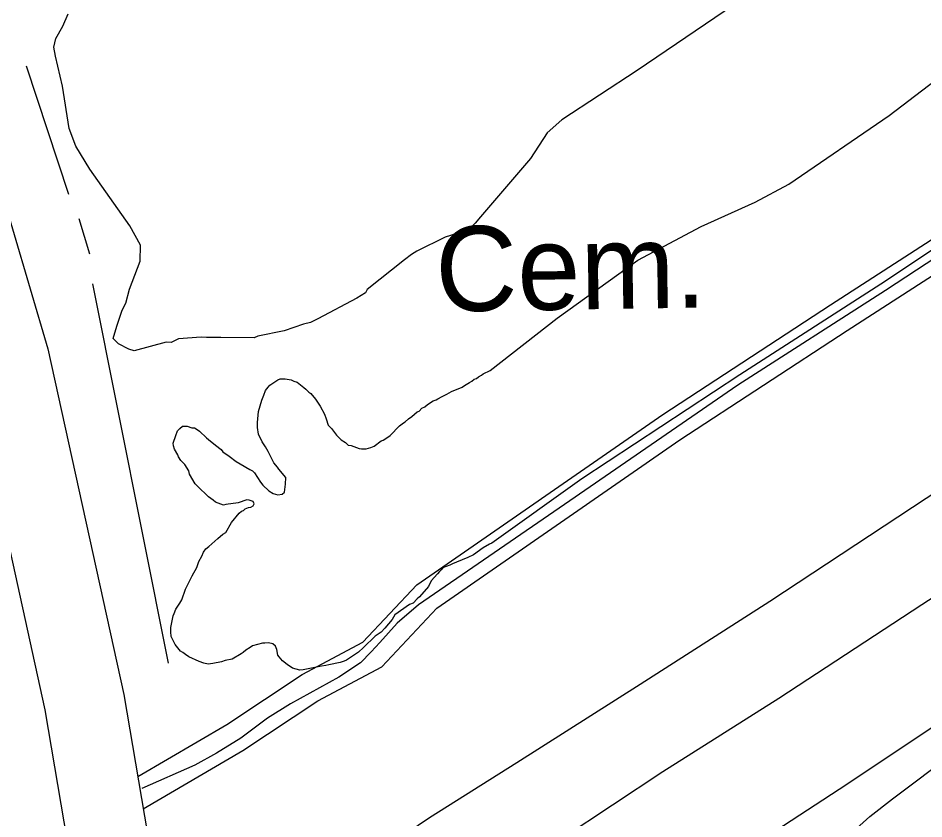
# Model space of a CAD drawing. Extents: x 3812694 to 3850888, y 319753 to 345638.
# Drawn here: x 3827334 to 3828221, y 341766 to 342550 of the extents above; entities that cross this region are included whole.
import ezdxf

# ---------------------------------------------------------------- set-up
doc = ezdxf.new("R2010")
doc.units = 0
for name, color, linetype in [('V-DTCH-CNTR', 7, 'Continuous'), ('V-GRID-MAJR', 7, 'Continuous'), ('V-ROAD-CNTR', 7, 'Continuous'), ('V-SITE-OTLN-IDEN', 7, 'Continuous'), ('V-SITE-VEGE', 7, 'Continuous'), ('V-TOPO-SHOR', 7, 'Continuous')]:
    doc.layers.add(name, color=color, linetype=linetype)

msp = doc.modelspace()

# ---------------------------------------------------------------- linework, layer by layer
at = {"layer": 'V-DTCH-CNTR'}
for points in [[(3828407.32, 342440.64), (3828293.22, 342355.47), (3828183.34, 342283.15), (3828038.76, 342190.5), (3827869.24, 342073.82), (3827726.16, 341975.48), (3827705.4, 341957.61), (3827688.23, 341938.67), (3827679.91, 341929.46), (3827669.51, 341918.72), (3827648.26, 341904.45)], [(3827648.26, 341904.45), (3827601.05, 341878.45), (3827578.41, 341864.28), (3827552.23, 341844.69), (3827528.42, 341830.14), (3827507.35, 341818.28), (3827455.46, 341795.38)]]:
    msp.add_lwpolyline(points, dxfattribs=at)
at = {"layer": 'V-GRID-MAJR'}
msp.add_spline([(3827552.14, 325339.08), (3827461.39, 331396.12), (3827370.6, 337456.24), (3827279.8, 343516.36), (3827279.75, 343519.45)], degree=3, dxfattribs=at)
at = {"layer": 'V-ROAD-CNTR'}
for points in [[(3826888.69, 343517.19), (3827149.47, 342673.63), (3827287.1, 342206.56), (3827360.53, 341872.65), (3827388.64, 341707), (3827434.74, 341341.67), (3827456.33, 341039.03), (3827475.62, 340587.6), (3827499.99, 340026.68), (3827519.29, 339556.06), (3827541.5, 339155.86), (3827581.61, 338852.35), (3827660.21, 338530.82), (3827812.32, 338143.51), (3827979.35, 337772.54), (3828135.82, 337439.21), (3828238.83, 337215.31)], [(3826963.8, 343518.33), (3827224.65, 342696.63), (3827363.29, 342226.13), (3827437.73, 341887.68), (3827466.42, 341718.5), (3827513, 341349.39), (3827534.83, 341043.51), (3827554.16, 340590.98), (3827578.53, 340030), (3827597.82, 339559.85), (3827619.83, 339163.19), (3827658.99, 338866.88), (3827735.32, 338554.63), (3827884.8, 338174.03), (3828050.78, 337805.38), (3828207.11, 337472.34), (3828311.02, 337246.48)], [(3827451.37, 341807.26), (3827538.52, 341858.26), (3827612.18, 341907.2), (3827671.88, 341938.99), (3827724.51, 341995.02), (3827965.3, 342161.9), (3828129.51, 342269.17), (3828228.2, 342332.88), (3828349.85, 342418.43), (3828421.72, 342473.79), (3828507.9, 342502.47), (3828619.95, 342540.26), (3828691.01, 342559.39)], [(3827456.73, 341775.64), (3827554.41, 341832.8), (3827627.57, 341881.41), (3827690.35, 341914.84), (3827744.21, 341972.17), (3827982.05, 342137.01), (3828145.85, 342244.01), (3828244.97, 342308), (3828367.64, 342394.27), (3828436.01, 342446.93), (3828517.43, 342474.02), (3828628.66, 342511.53), (3828696.72, 342529.86)]]:
    msp.add_lwpolyline(points, dxfattribs=at)
at = {"layer": 'V-SITE-VEGE'}
for points in [[(3828140.02, 342634.66), (3827940.42, 342498.79), (3827866.37, 342450.29), (3827852.25, 342437.78), (3827835.91, 342412.66), (3827787.04, 342355.54), (3827781.85, 342349.06), (3827776.64, 342343.92), (3827757.61, 342337.18), (3827752.42, 342335.5), (3827724.71, 342321.92), (3827719.51, 342318.52), (3827712.57, 342313.4), (3827676.12, 342284.37), (3827674.36, 342280.93), (3827665.7, 342275.83), (3827627.59, 342255.44), (3827620.66, 342252.05), (3827613.75, 342250.38), (3827594.72, 342243.63), (3827568.81, 342238.67), (3827565.34, 342236.97), (3827532.58, 342237.24), (3827518.78, 342237.35), (3827513.61, 342237.39), (3827491.17, 342235.85), (3827484.24, 342232.46), (3827479.07, 342232.5), (3827447.96, 342224.12), (3827442.8, 342225.89), (3827432.49, 342231.15)], [(3827432.49, 342231.15), (3827429.07, 342234.63), (3827427.36, 342236.37), (3827430.9, 342248.41), (3827436.2, 342263.89), (3827439.71, 342270.76), (3827443.27, 342284.53), (3827453.84, 342312.04), (3827453.97, 342327.57), (3827443.77, 342346.62), (3827404.55, 342402.13), (3827390.94, 342424.66), (3827384.18, 342441.96), (3827377.61, 342483.41), (3827370.95, 342512.79), (3827369.3, 342521.43), (3827371.09, 342530.04), (3827378.09, 342542.05), (3827383.36, 342554.08)], [(3827735.08, 342171.63), (3827740.63, 342175.29), (3827743.4, 342176.2), (3827745.25, 342177.11), (3827749.4, 342179.39), (3827754.03, 342181.67), (3827758.65, 342184.41), (3827768.81, 342188.51), (3827771.12, 342190.34), (3827774.36, 342192.17), (3827776.21, 342193.08), (3827778.52, 342194.45), (3827780.84, 342196.28), (3827783.15, 342197.19), (3827785, 342198.56), (3827787.77, 342200.39), (3827789.62, 342201.77), (3827796.51, 342204.82), (3827861.98, 342256.26), (3827940.77, 342312.83), (3828002.92, 342345.84), (3828055.71, 342369.65), (3828088.86, 342387.43), (3828186.87, 342454.71), (3828270.92, 342518.48)], [(3828303.25, 342372.29), (3828183.33, 342292.31), (3828040.87, 342200.7), (3827885.96, 342098.89), (3827797.97, 342035.79), (3827795.66, 342034.88), (3827789.65, 342031.23), (3827779.93, 342024.36), (3827774.39, 342021.63), (3827763.3, 342017.08), (3827759.6, 342015.71), (3827756.83, 342014.34), (3827753.14, 342012.98), (3827749.91, 342011.62), (3827748.51, 342009.78), (3827746.66, 342007.94), (3827744.8, 342005.65), (3827738.77, 341998.77), (3827735.98, 341993.25), (3827727.17, 341983.16), (3827724.86, 341981.33), (3827721.15, 341977.2), (3827717.45, 341975.84), (3827703.11, 341965.77), (3827700.32, 341961.18), (3827693.36, 341952.46), (3827689.66, 341948.79), (3827683.64, 341944.67), (3827672.52, 341933.67), (3827667.43, 341929.09), (3827655.86, 341921.31), (3827653.55, 341920.4), (3827649.4, 341919.04), (3827638.33, 341916.79), (3827635.56, 341915.89), (3827631.41, 341915.45), (3827613.41, 341911.86), (3827610.18, 341911.41), (3827602.82, 341913.29), (3827597.77, 341917.01), (3827593.18, 341920.72), (3827589.97, 341924.42), (3827588.6, 341926.27), (3827587.7, 341931.81), (3827586.34, 341935.04), (3827583.59, 341937.36), (3827579.44, 341938.31), (3827575.75, 341937.87), (3827573.45, 341937.88), (3827563.75, 341935.16), (3827561.44, 341933.79), (3827557.28, 341931.05), (3827554.5, 341928.76), (3827552.65, 341927.39), (3827543.87, 341922.36), (3827536.95, 341921.02), (3827533.25, 341919.65), (3827524.95, 341917.85), (3827520.33, 341917.41), (3827516.19, 341918.36), (3827511.59, 341919.77), (3827501.47, 341924.43), (3827498.26, 341926.75), (3827495.5, 341928.61), (3827493.21, 341930), (3827488.17, 341936.48), (3827484.06, 341944.34), (3827483.63, 341948.95), (3827483.65, 341953.1), (3827485.54, 341961.39), (3827486.02, 341964.61), (3827486.95, 341966.91), (3827488.81, 341971.05), (3827492.53, 341977.02), (3827494.39, 341980.24), (3827498.14, 341990.82), (3827500.93, 341996.79), (3827504.66, 342003.69), (3827509.31, 342011.96), (3827511.19, 342017.94), (3827513.98, 342023), (3827515.84, 342027.14), (3827518.17, 342030.35), (3827520.94, 342032.64), (3827529.74, 342040.43), (3827534.83, 342044.55), (3827537.61, 342046.38), (3827543.19, 342056.03), (3827550.61, 342065.21), (3827552.93, 342067.04), (3827554.77, 342067.95), (3827556.63, 342069.33), (3827559.86, 342070.69), (3827562.17, 342071.14), (3827564.48, 342072.51), (3827565.41, 342074.35), (3827564.5, 342076.66), (3827560.36, 342078.06), (3827558.05, 342078.08), (3827549.74, 342075.35), (3827537.75, 342073.57)], [(3827537.75, 342073.57), (3827535.45, 342073.13), (3827527.62, 342075.93), (3827525.33, 342077.79), (3827520.73, 342081.04), (3827517.98, 342083.82), (3827512.48, 342088.92), (3827507.44, 342094.01), (3827501.96, 342103.26), (3827501.51, 342106.49), (3827497.4, 342112.96), (3827493.73, 342116.67), (3827491.44, 342120.37), (3827490.53, 342122.22), (3827487.33, 342127.76), (3827486.43, 342131), (3827485.98, 342133.77), (3827488.79, 342141.12), (3827490.2, 342145.73), (3827492.51, 342148.02), (3827495.29, 342150.31), (3827499.9, 342150.28), (3827504.5, 342148.88), (3827506.8, 342148.86), (3827509.56, 342147.01), (3827511.85, 342145.61), (3827518.74, 342139.12), (3827520.57, 342137.27), (3827527.45, 342131.7), (3827532.96, 342127.53), (3827534.79, 342125.21), (3827540.76, 342121.03), (3827547.65, 342115.92), (3827551.79, 342113.6), (3827560.98, 342108.02), (3827563.73, 342106.62), (3827565.57, 342104.77), (3827571.51, 342095.52), (3827573.8, 342092.74), (3827579.76, 342087.18), (3827583.9, 342084.39), (3827588.5, 342082.98), (3827592.65, 342083.89), (3827594.96, 342085.72), (3827595.93, 342093.55), (3827596.43, 342100), (3827589.56, 342108.33), (3827588.18, 342110.18), (3827584.52, 342114.35), (3827579.04, 342125.44), (3827576.3, 342130.06), (3827573.1, 342135.15), (3827569.46, 342142.54), (3827568.57, 342149), (3827568.59, 342154.07), (3827569.57, 342164.67), (3827572.86, 342175.71), (3827574.73, 342180.77), (3827576.59, 342185.37), (3827578.92, 342188.59), (3827580.77, 342190.42), (3827588.63, 342195.91), (3827590.94, 342196.82), (3827595.55, 342196.79), (3827601.54, 342195.84), (3827604.3, 342194.44), (3827607.52, 342193.51), (3827613.94, 342188.4), (3827615.78, 342186.55), (3827618.99, 342183.77), (3827620.83, 342182.37), (3827625.41, 342176.82), (3827629.98, 342169.88), (3827634.08, 342162.02), (3827635.9, 342157.41), (3827637.72, 342151.4), (3827640.93, 342148.16), (3827645.96, 342141.68), (3827650.55, 342137.05), (3827654.68, 342134.26), (3827657.44, 342131.94), (3827660.2, 342131.47), (3827668.02, 342128.66), (3827670.32, 342128.18), (3827674.93, 342128.16), (3827679.54, 342129.52), (3827682.78, 342130.89), (3827689.72, 342135.92), (3827691.57, 342136.83), (3827696.19, 342139.57), (3827698.5, 342141.4), (3827707.77, 342150.57), (3827711.47, 342153.78), (3827713.32, 342154.69), (3827716.56, 342157.44), (3827719.8, 342159.73), (3827724.9, 342164.31), (3827726.75, 342165.22), (3827729.53, 342167.97), (3827732.3, 342169.34), (3827735.08, 342171.63)], [(3828325.33, 342044.75), (3828218.94, 341975.26), (3828079.11, 341883.62), (3827965.47, 341811.95), (3827817.43, 341713.77), (3827738.15, 341663.57), (3827643.65, 341603.38), (3827630.8, 341600.39), (3827618.38, 341601.66), (3827611.03, 341605.22), (3827601.04, 341617.73), (3827593.79, 341633.33), (3827590.43, 341649.28), (3827593.71, 341669.84), (3827605.08, 341682.17), (3827649.19, 341707.82), (3827737.09, 341767.28), (3827822.61, 341820.93), (3827943.28, 341897.59), (3828070.21, 341978.86), (3828307.24, 342135.34)], [(3828222.03, 341688.5), (3828213.87, 341691.3), (3828189.35, 341696.05), (3828170.51, 341691.06), (3828164.12, 341688.08), (3828155.62, 341685.73), (3828146.83, 341686.41), (3828135.38, 341694.69), (3828129.73, 341707.78), (3828135.99, 341731.37), (3828148.89, 341750.66), (3828168.14, 341768.08), (3828190.11, 341785.48), (3828211.17, 341801.07), (3828229.78, 341815.16)]]:
    msp.add_lwpolyline(points, dxfattribs=at)
at = {"layer": 'V-TOPO-SHOR'}
for p, q in [((3827383.85, 342377.11), (3827342.65, 342503.05)), ((3827404.48, 342318.77), (3827393.95, 342353.34)), ((3827481.55, 341918.13), (3827407.34, 342289.91))]:
    msp.add_line(p, q, dxfattribs=at)
msp.add_lwpolyline([(3828708.33, 342168.44), (3828512.47, 342042.68), (3828310.92, 341909.84), (3828138.05, 341794.54), (3827897.4, 341637.44), (3827711.57, 341510.52), (3827565.22, 341412.96)], dxfattribs=at)

# ---------------------------------------------------------------- texts
at = {"layer": 'V-SITE-OTLN-IDEN'}
msp.add_text('Cem.', height=83, rotation=0.84341, dxfattribs=at).set_placement((3827743.27, 342262.67))

doc.saveas('drawing.dxf')
